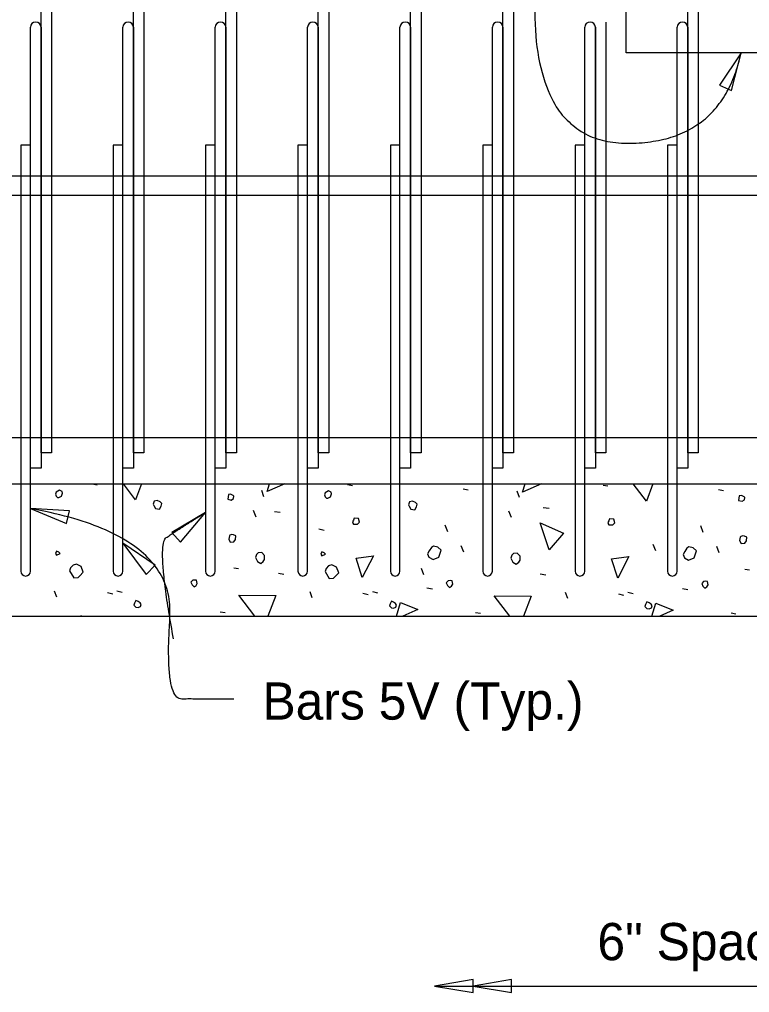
# Model space of a CAD drawing. Extents: x 120588.1 to 120659.6, y 120683.4 to 120715.5.
# Drawn here: x 120618.29 to 120622.24, y 120693.66 to 120698.93 of the extents above; entities that cross this region are included whole.
import ezdxf

# ---------------------------------------------------------------- set-up
doc = ezdxf.new("R2010")
doc.units = 0
for name, color, linetype in [('Dimension', 7, 'Continuous'), ('Patterning', 7, 'Continuous'), ('SheetBorder_dp', 7, 'Continuous'), ('SheetLines_dp', 7, 'Continuous'), ('SupstrConc', 7, 'Continuous')]:
    doc.layers.add(name, color=color, linetype=linetype)

msp = doc.modelspace()

# ---------------------------------------------------------------- linework, layer by layer
at = {"layer": 'Dimension'}
for p, q in [((120618.6847, 120696.4203), (120618.7112, 120696.415)), ((120619.6146, 120696.3496), (120619.6022, 120696.3832)), ((120620.0671, 120696.4168), (120620.0936, 120696.4115)), ((120620.6929, 120696.3921), (120620.7194, 120696.3868)), ((120620.997, 120696.3461), (120620.9846, 120696.3797)), ((120621.4495, 120696.4133), (120621.476, 120696.408)), ((120622.0753, 120696.3885), (120622.1018, 120696.3832)), ((120619.5721, 120696.24), (120619.558, 120696.2754)), ((120620.9545, 120696.2365), (120620.9404, 120696.2718)), ((120621.126, 120696.2913), (120621.1578, 120696.2878)), ((120619.6708, 120696.2698), (120619.7026, 120696.2663)), ((120619.9116, 120696.1764), (120619.9398, 120696.1693)), ((120620.6098, 120696.1605), (120620.5957, 120696.1958)), ((120621.9922, 120696.1569), (120621.9781, 120696.1923)), ((120620.6964, 120696.0491), (120620.6823, 120696.0845)), ((120621.7359, 120696.0562), (120621.7217, 120696.0915)), ((120622.0788, 120696.0456), (120622.0647, 120696.0809)), ((120619.4519, 120695.9643), (120619.4767, 120695.9607)), ((120620.479, 120695.9271), (120620.4666, 120695.9607)), ((120622.2167, 120695.9572), (120622.2415, 120695.9536)), ((120619.6925, 120695.936), (120619.7226, 120695.9307)), ((120621.1101, 120695.9324), (120621.1402, 120695.9271)), ((120620.4967, 120695.8564), (120620.5267, 120695.8511)), ((120621.8791, 120695.8529), (120621.9091, 120695.8476)), ((120618.4938, 120695.8052), (120618.4814, 120695.8387)), ((120618.7678, 120695.8317), (120618.7961, 120695.8246)), ((120618.8191, 120695.8405), (120618.8474, 120695.8334)), ((120619.8762, 120695.8016), (120619.8638, 120695.8352)), ((120620.1502, 120695.8281), (120620.1785, 120695.8211)), ((120620.2015, 120695.837), (120620.2298, 120695.8299)), ((120621.2586, 120695.7981), (120621.2462, 120695.8317)), ((120621.5326, 120695.8246), (120621.5609, 120695.8175)), ((120621.5839, 120695.8334), (120621.6121, 120695.8264)), ((120618.6211, 120695.7062), (120618.6335, 120695.7037)), ((120619.3777, 120695.7274), (120619.4042, 120695.7221)), ((120620.7601, 120695.7238), (120620.7866, 120695.7185)), ((120622.1425, 120695.7203), (120622.169, 120695.715))]:
    msp.add_line(p, q, dxfattribs=at)
for points in [[(120618.4973, 120696.3461), (120618.5044, 120696.3461), (120618.5186, 120696.3532), (120618.5239, 120696.3691), (120618.5221, 120696.3779), (120618.5079, 120696.385), (120618.4903, 120696.3744), (120618.4867, 120696.3638), (120618.4903, 120696.3532), (120618.4973, 120696.3461)], [(120618.9198, 120696.3337), (120618.854, 120696.4203)], [(120618.9522, 120696.4203), (120618.9198, 120696.3337)], [(120619.6322, 120696.3779), (120619.6453, 120696.4203)], [(120619.7267, 120696.4203), (120619.6322, 120696.3779)], [(120619.9532, 120696.3426), (120619.9602, 120696.3426), (120619.9744, 120696.3496), (120619.9797, 120696.3655), (120619.9779, 120696.3744), (120619.9638, 120696.3814), (120619.9461, 120696.3708), (120619.9426, 120696.3602), (120619.9461, 120696.3496), (120619.9532, 120696.3426)], [(120621.0146, 120696.3744), (120621.0288, 120696.4203)], [(120621.1169, 120696.4203), (120621.0146, 120696.3744)], [(120621.6846, 120696.3266), (120621.6134, 120696.4203)], [(120621.7196, 120696.4203), (120621.6846, 120696.3266)], [(120619.0188, 120696.3019), (120619.0277, 120696.286), (120619.0489, 120696.2825), (120619.0577, 120696.2984), (120619.0613, 120696.3125), (120619.0524, 120696.3213), (120619.0365, 120696.3302), (120619.0206, 120696.3249), (120619.0153, 120696.309), (120619.0188, 120696.3019)], [(120619.4183, 120696.3373), (120619.4378, 120696.332), (120619.4502, 120696.3408), (120619.4519, 120696.3532), (120619.4484, 120696.3567), (120619.4343, 120696.3638), (120619.4219, 120696.362), (120619.4201, 120696.3496), (120619.4183, 120696.3373)], [(120620.4012, 120696.2984), (120620.4101, 120696.2825), (120620.4313, 120696.2789), (120620.4401, 120696.2948), (120620.4437, 120696.309), (120620.4348, 120696.3178), (120620.4189, 120696.3266), (120620.403, 120696.3213), (120620.3977, 120696.3054), (120620.4012, 120696.2984)], [(120622.1831, 120696.3302), (120622.2026, 120696.3249), (120622.215, 120696.3337), (120622.2167, 120696.3461), (120622.2132, 120696.3496), (120622.199, 120696.3567), (120622.1867, 120696.3549), (120622.1849, 120696.3426), (120622.1831, 120696.3302)], [(120620.0989, 120696.2011), (120620.1202, 120696.2011), (120620.1308, 120696.2117), (120620.1255, 120696.2312), (120620.1025, 120696.233), (120620.0989, 120696.2224), (120620.0936, 120696.2135), (120620.0989, 120696.2011), (120620.0954, 120696.2047)], [(120621.4813, 120696.1976), (120621.5025, 120696.1976), (120621.5132, 120696.2082), (120621.5078, 120696.2277), (120621.4849, 120696.2294), (120621.4813, 120696.2188), (120621.476, 120696.21), (120621.4813, 120696.1976), (120621.4778, 120696.2011)], [(120621.1578, 120696.0615), (120621.1101, 120696.2082), (120621.2356, 120696.1534), (120621.1578, 120696.0615)], [(120619.4237, 120696.1198), (120619.4325, 120696.1039), (120619.4519, 120696.1057), (120619.4608, 120696.1181), (120619.4625, 120696.1375), (120619.4502, 120696.1428), (120619.4413, 120696.1446), (120619.4307, 120696.141), (120619.4272, 120696.1375), (120619.4237, 120696.1198)], [(120622.1884, 120696.1127), (120622.1973, 120696.0968), (120622.2167, 120696.0986), (120622.2256, 120696.111), (120622.2273, 120696.1304), (120622.215, 120696.1357), (120622.2061, 120696.1375), (120622.1955, 120696.134), (120622.192, 120696.1304), (120622.1884, 120696.1127)], [(120620.5073, 120696.0226), (120620.5303, 120696.0102), (120620.5603, 120696.0226), (120620.5727, 120696.0597), (120620.555, 120696.0774), (120620.532, 120696.0827), (120620.5214, 120696.0756), (120620.5091, 120696.0562), (120620.5002, 120696.0403), (120620.5073, 120696.0226)], [(120621.8897, 120696.0191), (120621.9127, 120696.0067), (120621.9427, 120696.0191), (120621.9551, 120696.0562), (120621.9374, 120696.0739), (120621.9144, 120696.0792), (120621.9038, 120696.0721), (120621.8915, 120696.0526), (120621.8826, 120696.0367), (120621.8897, 120696.0191)], [(120618.492, 120696.0332), (120618.5115, 120696.042), (120618.5044, 120696.0491), (120618.492, 120696.0544), (120618.4867, 120696.042), (120618.492, 120696.0332)], [(120619.5686, 120696.0208), (120619.5792, 120695.9996), (120619.5969, 120695.989), (120619.611, 120695.9996), (120619.6181, 120696.0102), (120619.6181, 120696.0314), (120619.6022, 120696.0473), (120619.5828, 120696.0456), (120619.5739, 120696.0367), (120619.5686, 120696.0208)], [(120619.9277, 120696.0297), (120619.9472, 120696.0385), (120619.9401, 120696.0456), (120619.9277, 120696.0509), (120619.9224, 120696.0385), (120619.9277, 120696.0297)], [(120620.1467, 120695.913), (120620.1131, 120696.0173), (120620.2068, 120696.0297), (120620.1467, 120695.913)], [(120620.951, 120696.0173), (120620.9616, 120695.9961), (120620.9793, 120695.9855), (120620.9934, 120695.9961), (120621.0005, 120696.0067), (120621.0005, 120696.0279), (120620.9846, 120696.0438), (120620.9651, 120696.042), (120620.9563, 120696.0332), (120620.951, 120696.0173)], [(120621.5291, 120695.9095), (120621.4955, 120696.0138), (120621.5892, 120696.0261), (120621.5291, 120695.9095)], [(120618.5627, 120695.9483), (120618.5857, 120695.9112), (120618.6087, 120695.913), (120618.6176, 120695.9218), (120618.637, 120695.9413), (120618.6246, 120695.9713), (120618.5999, 120695.9855), (120618.5822, 120695.9784), (120618.5681, 120695.9643), (120618.5627, 120695.9483)], [(120619.9451, 120695.9448), (120619.9681, 120695.9077), (120619.9911, 120695.9095), (120619.9999, 120695.9183), (120620.0194, 120695.9377), (120620.007, 120695.9678), (120619.9823, 120695.9819), (120619.9646, 120695.9749), (120619.9504, 120695.9607), (120619.9451, 120695.9448)], [(120619.2257, 120695.8723), (120619.2363, 120695.8617), (120619.2469, 120695.8688), (120619.2539, 120695.8794), (120619.2504, 120695.8971), (120619.2416, 120695.8988), (120619.2292, 120695.8971), (120619.2186, 120695.8865), (120619.2257, 120695.8723)], [(120620.6081, 120695.8688), (120620.6187, 120695.8582), (120620.6293, 120695.8653), (120620.6363, 120695.8759), (120620.6328, 120695.8935), (120620.624, 120695.8953), (120620.6116, 120695.8935), (120620.601, 120695.8829), (120620.6081, 120695.8688)], [(120621.9904, 120695.8653), (120622.0011, 120695.8547), (120622.0117, 120695.8617), (120622.0187, 120695.8723), (120622.0152, 120695.89), (120622.0064, 120695.8918), (120621.994, 120695.89), (120621.9834, 120695.8794), (120621.9904, 120695.8653)], [(120619.565, 120695.7037), (120619.4785, 120695.8175), (120619.6782, 120695.8158), (120619.6363, 120695.7037)], [(120620.9447, 120695.7037), (120620.8608, 120695.814), (120621.0606, 120695.8122), (120621.02, 120695.7037)], [(120618.9216, 120695.7521), (120618.934, 120695.7504), (120618.9464, 120695.7557), (120618.9499, 120695.7663), (120618.9446, 120695.7751), (120618.934, 120695.7822), (120618.9216, 120695.7875), (120618.9145, 120695.7733), (120618.911, 120695.7627), (120618.9216, 120695.7521)], [(120620.304, 120695.7486), (120620.3164, 120695.7468), (120620.3287, 120695.7521), (120620.3323, 120695.7627), (120620.327, 120695.7716), (120620.3164, 120695.7786), (120620.304, 120695.7839), (120620.2969, 120695.7698), (120620.2934, 120695.7592), (120620.304, 120695.7486)], [(120620.331, 120695.7037), (120620.3535, 120695.7769), (120620.4472, 120695.7397), (120620.3669, 120695.7037)], [(120621.6864, 120695.7451), (120621.6988, 120695.7433), (120621.7111, 120695.7486), (120621.7147, 120695.7592), (120621.7094, 120695.768), (120621.6988, 120695.7751), (120621.6864, 120695.7804), (120621.6793, 120695.7663), (120621.6758, 120695.7557), (120621.6864, 120695.7451)], [(120621.7145, 120695.7037), (120621.7359, 120695.7733), (120621.8296, 120695.7362), (120621.7572, 120695.7037)]]:
    msp.add_lwpolyline(points, dxfattribs=at)
at = {"layer": 'SheetBorder_dp'}
for p, q in [((120621.5747, 120698.7537), (120621.5747, 120699.087)), ((120624.5747, 120698.7537), (120621.5747, 120698.7537)), ((120615.4532, 120698.0869), (120624.5747, 120698.0869)), ((120615.4532, 120697.9828), (120624.5747, 120697.9828)), ((120615.4532, 120696.6703), (120624.5747, 120696.6703)), ((120615.4532, 120696.4203), (120624.5747, 120696.4203)), ((120615.4532, 120695.7037), (120624.5747, 120695.7037))]:
    msp.add_line(p, q, dxfattribs=at)
at = {"layer": 'SheetLines_dp'}
msp.add_line((120620.5378, 120693.7002), (120628.3661, 120693.7002), dxfattribs=at)
for points in [[(120622.1969, 120698.7537), (120622.08, 120698.5778), (120622.1445, 120698.5491)], [(120618.3507, 120696.2866), (120618.5454, 120696.2047), (120618.5615, 120696.2734)], [(120619.2986, 120696.2643), (120619.1166, 120696.157), (120619.1621, 120696.1031)], [(120618.8507, 120696.0979), (120618.9771, 120695.9286), (120619.0257, 120695.9797)], [(120620.5378, 120693.7002), (120620.7461, 120693.6649), (120620.7461, 120693.7355)], [(120620.7461, 120693.7002), (120620.9543, 120693.6649), (120620.9543, 120693.7355)]]:
    msp.add_lwpolyline(points, close=True, dxfattribs=at)
for points in [[(120620.9902, 120701.1889), (120621.2315, 120701.1889), (120621.4461, 120701.0816), (120621.0796, 120699.7399), (120621.0796, 120698.2641), (120622.0896, 120698.2641), (120622.1969, 120698.7537)], [(120619.4518, 120695.2544), (120619.2598, 120695.2544), (120619.0767, 120695.2544), (120619.1348, 120696.1436), (120618.3507, 120696.2866)], [(120619.1253, 120695.5795), (120619.0321, 120696.09), (120619.1393, 120696.166), (120619.2986, 120696.2643)]]:
    msp.add_open_spline(points, degree=2, dxfattribs=at)
at = {"layer": 'SupstrConc'}
for p, q in [((120618.3507, 120696.5037), (120618.3507, 120698.8917)), ((120618.408, 120698.8917), (120618.408, 120696.5037)), ((120618.8507, 120696.5037), (120618.8507, 120698.8917)), ((120618.908, 120698.8917), (120618.908, 120696.5037)), ((120619.3507, 120696.5037), (120619.3507, 120698.8917)), ((120619.408, 120698.8917), (120619.408, 120696.5037)), ((120619.8507, 120696.5037), (120619.8507, 120698.8917)), ((120619.908, 120698.8917), (120619.908, 120696.5037)), ((120620.3507, 120696.5037), (120620.3507, 120698.8917)), ((120620.408, 120698.8917), (120620.408, 120696.5037)), ((120620.8507, 120696.5037), (120620.8507, 120698.8917)), ((120620.908, 120698.8917), (120620.908, 120696.5037)), ((120621.3507, 120696.5037), (120621.3507, 120698.8917)), ((120621.408, 120698.8917), (120621.408, 120696.5037)), ((120621.8507, 120696.5037), (120621.8507, 120698.8917)), ((120621.908, 120698.8917), (120621.908, 120696.5037)), ((120618.3507, 120698.2537), (120618.2986, 120698.2537)), ((120618.2986, 120698.2537), (120618.2986, 120695.9464)), ((120618.3507, 120695.9464), (120618.3507, 120698.2537)), ((120618.8507, 120698.2537), (120618.7986, 120698.2537)), ((120618.7986, 120698.2537), (120618.7986, 120695.9464)), ((120618.8507, 120695.9464), (120618.8507, 120698.2537)), ((120619.3507, 120698.2537), (120619.2986, 120698.2537)), ((120619.2986, 120698.2537), (120619.2986, 120695.9464)), ((120619.3507, 120695.9464), (120619.3507, 120698.2537)), ((120619.8507, 120698.2537), (120619.7986, 120698.2537)), ((120619.7986, 120698.2537), (120619.7986, 120695.9464)), ((120619.8507, 120695.9464), (120619.8507, 120698.2537)), ((120620.3507, 120698.2537), (120620.2986, 120698.2537)), ((120620.2986, 120698.2537), (120620.2986, 120695.9464)), ((120620.3507, 120695.9464), (120620.3507, 120698.2537)), ((120620.8507, 120698.2537), (120620.7986, 120698.2537)), ((120620.7986, 120698.2537), (120620.7986, 120695.9464)), ((120620.8507, 120695.9464), (120620.8507, 120698.2537)), ((120621.3507, 120698.2537), (120621.2986, 120698.2537)), ((120621.2986, 120698.2537), (120621.2986, 120695.9464)), ((120621.3507, 120695.9464), (120621.3507, 120698.2537)), ((120621.8507, 120698.2537), (120621.7986, 120698.2537)), ((120621.7986, 120698.2537), (120621.7986, 120695.9464)), ((120621.8507, 120695.9464), (120621.8507, 120698.2537)), ((120618.408, 120696.5037), (120618.3507, 120696.5037)), ((120618.908, 120696.5037), (120618.8507, 120696.5037)), ((120619.408, 120696.5037), (120619.3507, 120696.5037)), ((120619.908, 120696.5037), (120619.8507, 120696.5037)), ((120620.408, 120696.5037), (120620.3507, 120696.5037)), ((120620.908, 120696.5037), (120620.8507, 120696.5037)), ((120621.408, 120696.5037), (120621.3507, 120696.5037)), ((120621.908, 120696.5037), (120621.8507, 120696.5037))]:
    msp.add_line(p, q, dxfattribs=at)
for points in [[(120618.408, 120699.6827), (120618.4653, 120699.6827), (120618.4653, 120696.587), (120618.408, 120696.587)], [(120618.908, 120699.6202), (120618.9653, 120699.6202), (120618.9653, 120696.587), (120618.908, 120696.587)], [(120619.408, 120699.5577), (120619.4653, 120699.5577), (120619.4653, 120696.587), (120619.408, 120696.587)], [(120619.908, 120699.4952), (120619.9653, 120699.4952), (120619.9653, 120696.587), (120619.908, 120696.587)], [(120620.408, 120699.4327), (120620.4653, 120699.4327), (120620.4653, 120696.587), (120620.408, 120696.587)], [(120620.908, 120699.3702), (120620.9653, 120699.3702), (120620.9653, 120696.587), (120620.908, 120696.587)], [(120621.908, 120699.2453), (120621.9653, 120699.2453), (120621.9653, 120696.587), (120621.908, 120696.587)]]:
    msp.add_lwpolyline(points, close=True, dxfattribs=at)
msp.add_lwpolyline([(120621.4653, 120698.9204), (120621.4653, 120696.587), (120621.408, 120696.587), (120621.408, 120698.8917)], dxfattribs=at)
for centre, radius, start, end in [((120618.3794, 120698.8917), 0.0286, 0, 180), ((120618.8794, 120698.8917), 0.0286, 0, 180), ((120619.3794, 120698.8917), 0.0286, 0, 180), ((120619.8794, 120698.8917), 0.0286, 0, 180), ((120620.3794, 120698.8917), 0.0286, 0, 180), ((120620.8794, 120698.8917), 0.0286, 0, 180), ((120621.3794, 120698.8917), 0.0286, 0, 180), ((120621.8794, 120698.8917), 0.0286, 0, 180), ((120618.3247, 120695.9464), 0.026, 180, 0), ((120618.8247, 120695.9464), 0.026, 180, 0), ((120619.3247, 120695.9464), 0.026, 180, 0), ((120619.8247, 120695.9464), 0.026, 180, 0), ((120620.3247, 120695.9464), 0.026, 180, 0), ((120620.8247, 120695.9464), 0.026, 180, 0), ((120621.3247, 120695.9464), 0.026, 180, 0), ((120621.8247, 120695.9464), 0.026, 180, 0)]:
    msp.add_arc(centre, radius, start, end, dxfattribs=at)

# ---------------------------------------------------------------- texts
at = {"layer": 'Patterning'}
for s, p in [('Bars 5V (Typ.)', (120619.6063, 120695.1427)), ('6" Spacing (Typ.)', (120621.4191, 120693.84))]:
    msp.add_text(s, height=0.2016, dxfattribs=at).set_placement(p)

doc.saveas('drawing.dxf')
